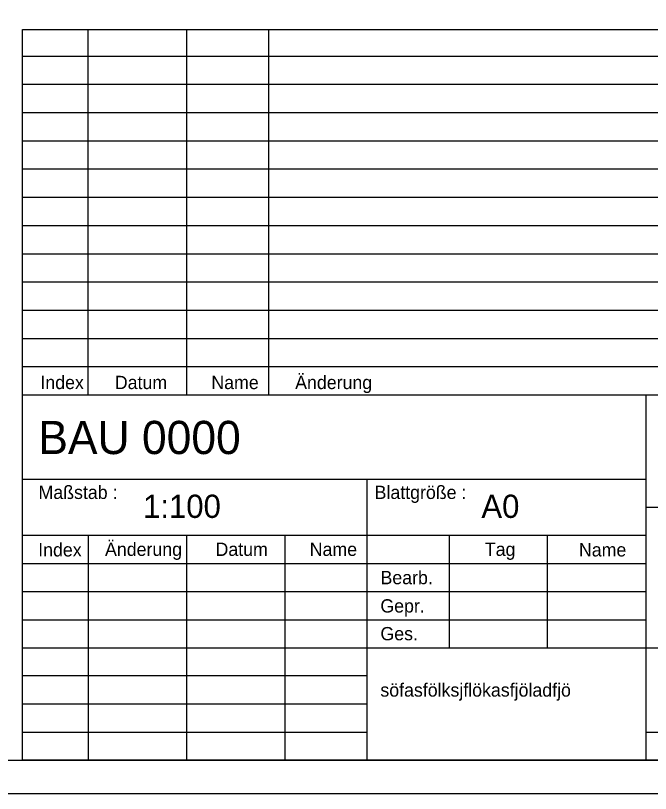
# Model space of a CAD drawing. Extents: x 0 to 119, y 0 to 84.
# Drawn here: x 100.51 to 110.07, y 0 to 11.71 of the extents above; entities that cross this region are included whole.
import ezdxf

# ---------------------------------------------------------------- set-up
doc = ezdxf.new("R2010")
doc.units = 0
doc.layers.add('90_Plankopf', color=7, linetype='Continuous')

msp = doc.modelspace()

# ---------------------------------------------------------------- linework, layer by layer
at = {"layer": '90_Plankopf'}
for p, q in [((100.612, 5.999), (100.612, 11.498)), ((100.612, 11.498), (118.4, 11.498)), ((100.612, 5.999), (100.612, 11.498)), ((100.612, 11.498), (118.4, 11.498)), ((101.6, 5.999), (101.6, 11.498)), ((101.6, 5.999), (101.6, 11.498)), ((103.083, 5.999), (103.083, 11.498)), ((103.083, 5.999), (103.083, 11.498)), ((104.318, 5.999), (104.318, 11.498)), ((104.318, 5.999), (104.318, 11.498)), ((100.612, 11.099), (118.4, 11.099)), ((100.612, 11.099), (118.4, 11.099)), ((100.612, 10.674), (118.4, 10.674)), ((100.612, 10.674), (118.4, 10.674)), ((100.612, 10.249), (118.4, 10.249)), ((100.612, 10.249), (118.4, 10.249)), ((100.612, 9.824), (118.4, 9.824)), ((100.612, 9.824), (118.4, 9.824)), ((100.612, 9.399), (118.4, 9.399)), ((100.612, 9.399), (118.4, 9.399)), ((100.612, 8.974), (118.4, 8.974)), ((100.612, 8.974), (118.4, 8.974)), ((100.612, 8.549), (118.4, 8.549)), ((100.612, 8.549), (118.4, 8.549)), ((100.612, 8.124), (118.4, 8.124)), ((100.612, 8.124), (118.4, 8.124)), ((100.612, 7.699), (118.4, 7.699)), ((100.612, 7.699), (118.4, 7.699)), ((100.612, 7.274), (118.4, 7.274)), ((100.612, 7.274), (118.4, 7.274)), ((100.612, 6.849), (118.4, 6.849)), ((100.612, 6.849), (118.4, 6.849)), ((100.612, 6.424), (118.4, 6.424)), ((100.612, 6.424), (118.4, 6.424)), ((100.612, 5.999), (118.4, 5.999)), ((100.612, 0.5), (100.612, 5.999)), ((100.612, 5.999), (118.4, 5.999)), ((100.612, 5.999), (118.4, 5.999)), ((100.612, 0.5), (100.612, 5.999)), ((100.612, 5.999), (118.4, 5.999)), ((110, 0.5), (110, 5.999)), ((110, 0.5), (110, 5.999)), ((100.612, 4.73), (110, 4.73)), ((100.612, 4.73), (110, 4.73)), ((105.8, 0.5), (105.8, 4.73)), ((105.8, 0.5), (105.8, 4.73)), ((110, 4.307), (118.4, 4.307)), ((110, 4.307), (118.4, 4.307)), ((100.612, 3.887), (110, 3.887)), ((100.612, 3.887), (110, 3.887)), ((101.6, 3.884), (101.6, 0.5)), ((101.6, 3.884), (101.6, 0.5)), ((103.083, 0.5), (103.083, 3.884)), ((103.083, 0.5), (103.083, 3.884)), ((104.565, 0.5), (104.565, 3.884)), ((104.565, 0.5), (104.565, 3.884)), ((107.035, 3.884), (107.035, 2.192)), ((107.035, 3.884), (107.035, 2.192)), ((108.518, 2.192), (108.518, 3.884)), ((108.518, 2.192), (108.518, 3.884)), ((100.612, 3.463), (110, 3.463)), ((100.612, 3.463), (110, 3.463)), ((100.612, 3.038), (110, 3.038)), ((100.612, 3.038), (110, 3.038)), ((100.612, 2.615), (110, 2.615)), ((100.612, 2.615), (110, 2.615)), ((100.612, 2.192), (110, 2.192)), ((100.612, 2.192), (110, 2.192)), ((100.612, 2.192), (110, 2.192)), ((100.612, 2.192), (110, 2.192)), ((105.8, 2.192), (110, 2.192)), ((105.8, 2.192), (110, 2.192)), ((110, 2.192), (118.4, 2.192)), ((110, 2.192), (118.4, 2.192)), ((105.8, 1.769), (100.612, 1.769)), ((105.8, 1.769), (100.612, 1.769)), ((105.8, 1.346), (100.612, 1.346)), ((105.8, 1.346), (100.612, 1.346)), ((100.612, 0.923), (105.8, 0.923)), ((100.612, 0.923), (105.8, 0.923)), ((110, 0.923), (118.4, 0.923)), ((110, 0.923), (118.4, 0.923)), ((118.4, 0.5), (100.612, 0.5)), ((100.612, 0.5), (105.8, 0.5)), ((118.4, 0.5), (100.612, 0.5)), ((100.612, 0.5), (105.8, 0.5)), ((101.78, 0.5), (118.4, 0.5)), ((101.78, 0.5), (118.4, 0.5)), ((101.78, 0.5), (118.4, 0.5)), ((101.78, 0.5), (118.4, 0.5))]:
    msp.add_line(p, q, dxfattribs=at)
for points in [[(0, 0), (118.9, 0), (118.9, 84.1), (0, 84.1)], [(0, 0), (118.9, 0), (118.9, 84.1), (0, 84.1)], [(2.5, 0.5), (118.4, 0.5), (118.4, 83.6), (2.5, 83.6)], [(2.5, 0.5), (118.4, 0.5), (118.4, 83.6), (2.5, 83.6)]]:
    msp.add_lwpolyline(points, close=True, dxfattribs=at)

# ---------------------------------------------------------------- texts
for s, height, p in [('Änderung', 0.2, (104.716, 6.086)), ('Änderung', 0.2, (104.716, 6.086)), ('Index', 0.2, (100.88, 6.086)), ('Index', 0.2, (100.88, 6.086)), ('Datum', 0.2, (102.001, 6.086)), ('Datum', 0.2, (102.001, 6.086)), ('Name', 0.2, (103.454, 6.086)), ('Name', 0.2, (103.454, 6.086)), ('BAU 0000      ', 0.5, (100.849, 5.108)), ('BAU 0000      ', 0.5, (100.849, 5.108)), ('Maßstab :', 0.2, (100.852, 4.432)), ('Maßstab :', 0.2, (100.852, 4.432)), ('Blattgröße :', 0.19999, (105.912, 4.432)), ('Blattgröße :', 0.19999, (105.912, 4.432)), ('1:100    ', 0.35, (102.426, 4.147)), ('1:100    ', 0.35, (102.426, 4.147)), ('A0       ', 0.35, (107.52, 4.147)), ('A0       ', 0.35, (107.52, 4.147)), ('Index', 0.2, (100.847, 3.567)), ('Index', 0.2, (100.847, 3.567)), ('Änderung', 0.2, (101.853, 3.575)), ('Änderung', 0.2, (101.853, 3.575)), ('Datum', 0.2, (103.517, 3.575)), ('Datum', 0.2, (103.517, 3.575)), ('Name', 0.2, (104.935, 3.575)), ('Name', 0.2, (104.935, 3.575)), ('Tag', 0.2, (107.572, 3.575)), ('Tag', 0.2, (107.572, 3.575)), ('Name', 0.2, (108.989, 3.567)), ('Name', 0.2, (108.989, 3.567)), ('Bearb.', 0.2, (106.001, 3.149)), ('Bearb.', 0.2, (106.001, 3.149)), ('Gepr.', 0.2, (105.999, 2.723)), ('Gepr.', 0.2, (105.999, 2.723)), ('Ges.', 0.2, (106, 2.305)), ('Ges.', 0.2, (106, 2.305)), ('söfasfölksjflökasfjöladfjö', 0.2, (105.999, 1.457))]:
    msp.add_text(s, height=height, dxfattribs=at).set_placement(p)

doc.saveas('drawing.dxf')
